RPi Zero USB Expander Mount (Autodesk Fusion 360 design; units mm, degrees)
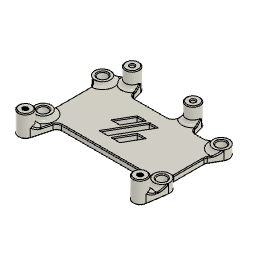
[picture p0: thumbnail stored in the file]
sketch "Sketch1" plane through (0, 0, 0) normal (0, 0, 1) x axis (1, 0, 0)
  line L1 (-32.5, 26.25) -> (32.5, 26.25)
  line L2 (-32.5, -26.25) -> (-32.5, 26.25)
  line L3 (32.5, -26.25) -> (-32.5, -26.25)
  line L4 (32.5, 26.25) -> (32.5, -26.25)
  line L5 (-32.5, -26.25) -> (32.5, 26.25)
  line L6 (32.5, -26.25) -> (-32.5, 26.25)
  line L7 (29, 0.25) -> (-29, 0.25)
  line L8 (29, -22.75) -> (29, 0.25)
  line L9 (-29, -22.75) -> (29, -22.75)
  line L10 (-29, 0.25) -> (-29, -22.75)
  line L11 (-5.77, 23) -> (-20.77, 23)
  line L12 (10.03, 23) -> (-5.77, 23)
  circle C1 centre (-20.77, 23) radius 1.25
  circle C2 centre (-5.77, 23) radius 1.25
  circle C3 centre (10.03, 23) radius 1.25
  circle C4 centre (-29, 0.25) radius 1.25
  circle C5 centre (29, 0.25) radius 1.25
  circle C6 centre (29, -22.75) radius 1.25
  circle C7 centre (-29, -22.75) radius 1.25
  point P6 (0, 0)
  point P1 (0, 0)
  point P10 (-29, 0.25)
  point P11 (-29, 0.25)
  point P12 (29, 0.25)
  point P15 (29, 0.25)
  point P13 (29, -22.75)
  point P16 (29, -22.75)
  point P14 (-29, -22.75)
  point P17 (-29, -22.75)
  point P7 (-20.77, 23)
  point P18 (-20.77, 23)
  point P8 (-5.77, 23)
  point P19 (-5.77, 23)
  point P9 (10.03, 23)
  point P20 (10.03, 23)
  point P4 (-32.5, -26.25)
  point P5 (32.5, -26.25)
  point P2 (32.5, 26.25)
  horizontal L1
  perpendicular L1 L2
  parallel L1 L3
  parallel L2 L4
  coincident L5 P6
  coincident L6 P6
  coincident P1 P6
  horizontal L7
  vertical L8
  horizontal L9
  vertical L10
  coincident P10 P11
  coincident P12 P15
  coincident P13 P16
  coincident P14 P17
  equal C6 C7
  equal C5 C6
  equal C4 C5
  equal C1 C4
  equal C1 C3
  equal C2 C3
  horizontal L11
  parallel L11 L12
  coincident P7 P18
  coincident P8 P19
  coincident P9 P20
  dimension "d1" distance P4 P5 = 65
  dimension "d2" distance P2 P5 = 52.5
  dimension "d3" distance P11 P14 = 23
  dimension "d4" distance P13 P14 = 58
  dimension "d5" diameter C1 = 2.5
  dimension "d10" distance L3 L9 = 3.5
  dimension "d11" distance L2 L10 = 3.5
  dimension "d12" distance P7 P10 = 8.23
  dimension "d13" distance P7 P10 = 22.75
  dimension "d14" distance P18 P19 = 15
  dimension "d15" distance P19 P20 = 15.8
  dimension "d27" diameter P15 = 8
  dimension "d47" angle P15 = 30
  dimension "d48" angle P15 = 30
extrude "Extrude1" new body sketch "Sketch1" profile of L1 L2 L3 L4 C1 C2 C3 C4 C5 C6 C7 along normal blind 1.6
fillet "Fillet1" radius 2
sketch "Sketch1" plane through (0, 0, 0) normal (0, 0, -1) x axis (1, 0, 0)
  line L1 (32.5, 24.25) -> (32.5, -24.25)
  line L2 (-30.5, 26.25) -> (30.5, 26.25)
  line L3 (-32.5, -24.25) -> (-32.5, 24.25)
  line L4 (30.5, -26.25) -> (-30.5, -26.25)
  circle C1 centre (29, -0.25) radius 1.25
  circle C2 centre (29, 22.75) radius 1.25
  circle C3 centre (-5.77, -23) radius 1.25
  circle C4 centre (10.03, -23) radius 1.25
  circle C5 centre (-20.77, -23) radius 1.25
  circle C6 centre (-29, 22.75) radius 1.25
  circle C7 centre (-29, -0.25) radius 1.25
  arc A1 centre (30.5, -24.25) radius 2 clockwise from (32.5, -24.25) to (30.5, -26.25)
  arc A2 centre (30.5, 24.25) radius 2 clockwise from (30.5, 26.25) to (32.5, 24.25)
  arc A3 centre (-30.5, 24.25) radius 2 clockwise from (-32.5, 24.25) to (-30.5, 26.25)
  arc A4 centre (-30.5, -24.25) radius 2 clockwise from (-30.5, -26.25) to (-32.5, -24.25)
  circle C8 centre (-29, 22.75) radius 3.5
  circle C9 centre (29, 22.75) radius 3.5
  circle C10 centre (-20.77, -23) radius 3.5
  circle C11 centre (10.03, -23) radius 3.5
  concentric C6 C8
  concentric C2 C9
  concentric C5 C10
  concentric C4 C11
  equal C9 C11
  equal C10 C11
  equal C8 C10
  dimension "d16" diameter C8 = 7
extrude "Extrude1" new body sketch "Sketch1" profile of C8 C9 C10 C11 along normal blind 11
sketch "Sketch2" plane through (0, 0, -11) normal (0, 0, -1) x axis (1, 0, 0)
  line L1 (30, 12.75) -> (-30, 12.75)
  line L2 (30, -17.25) -> (30, 12.75)
  line L3 (-30, -17.25) -> (30, -17.25)
  line L4 (-30, 12.75) -> (-30, -17.25)
  line L5 (29, 22.75) -> (-29, 22.75)
  line L6 (0, 12.75) -> (0, 22.75)
  line L7 (-22.4821, -26.0527) -> (-31.9567, -20.7387)
  line L8 (-32.461, 23.2711) -> (-33.9554, 13.3455)
  line L9 (33.9554, 13.3455) -> (32.461, 23.2711)
  line L10 (-30, -13.25) -> (-30, 8.75)
  line L11 (30, -13.25) -> (30, 8.75)
  line L12 (26, 12.75) -> (-26, 12.75)
  line L13 (22.697, 12.75) -> (25.6193, 23.6559)
  line L14 (-22.697, 12.75) -> (-25.6193, 23.6559)
  line L15 (26, -17.25) -> (-26, -17.25)
  line L16 (-15.6058, -17.25) -> (-17.3893, -23.9059)
  line L17 (6.6493, -23.9059) -> (4.8658, -17.25)
  line L18 (15.1942, -17.25) -> (13.4107, -23.9059)
  line L19 (30, -9.25) -> (33.4641, -15.25)
  line L20 (22, -17.25) -> (28, -20.7141)
  circle C1 centre (29, 22.75) radius 3.5
  circle C2 centre (-30, 12.75) radius 2.35
  circle C3 centre (-30, -17.25) radius 2.35
  circle C4 centre (30, -17.25) radius 2.35
  circle C5 centre (30, 12.75) radius 2.35
  circle C6 centre (10.03, -23) radius 3.5
  circle C7 centre (-20.77, -23) radius 3.5
  circle C8 centre (-29, 22.75) radius 3.5
  circle C9 centre (-30, -17.25) radius 4
  circle C10 centre (30, -17.25) radius 4
  circle C11 centre (-30, 12.75) radius 4
  circle C12 centre (30, 12.75) radius 4
  point P3 (-30, 12.75)
  point P7 (-30, 12.75)
  point P6 (-30, -17.25)
  point P8 (-30, -17.25)
  point P5 (30, -17.25)
  point P9 (30, -17.25)
  point P4 (30, 12.75)
  point P10 (30, 12.75)
  point P13 (-29, 22.75)
  point P14 (-29, 22.75)
  point P2 (29, 22.75)
  point P15 (29, 22.75)
  point P16 (0, 22.75)
  point P17 (0, 12.75)
  point P23 (-22.4821, -26.0527)
  point P24 (-33.9554, 13.3455)
  point P25 (-32.461, 23.2711)
  point P26 (32.461, 23.2711)
  point P27 (33.9554, 13.3455)
  point P28 (-30, 8.75)
  point P29 (-30, -13.25)
  point P30 (30, 8.75)
  point P31 (30, -13.25)
  point P32 (-26, 12.75)
  point P33 (26, 12.75)
  point P34 (25.6193, 23.6559)
  point P35 (22.697, 12.75)
  point P36 (-25.6193, 23.6559)
  point P37 (-22.697, 12.75)
  point P38 (-26, -17.25)
  point P39 (26, -17.25)
  point P22 (-31.9567, -20.7387)
  point P40 (-17.3893, -23.9059)
  point P41 (-15.6058, -17.25)
  point P42 (4.8658, -17.25)
  point P43 (6.6493, -23.9059)
  point P44 (13.4107, -23.9059)
  point P45 (15.1942, -17.25)
  point P46 (33.4641, -15.25)
  point P47 (30, -9.25)
  point P48 (28, -20.7141)
  point P49 (22, -17.25)
  horizontal L1
  vertical L2
  horizontal L3
  vertical L4
  coincident P3 P7
  coincident P6 P8
  coincident P5 P9
  coincident P4 P10
  equal C2 C3
  equal C3 C5
  equal C4 C5
  coincident P13 P14
  coincident P2 P15
  midpoint L5 P16
  perpendicular L5 L6
  midpoint L1 P17
  concentric C3 C9
  concentric C4 C10
  equal C9 C10
  concentric C2 C11
  concentric C5 C12
  equal C11 C12
  equal C10 C12
  coincident C7 P23
  tangent C7 L7
  coincident C11 P24
  coincident C8 P25
  coincident C1 P26
  coincident C12 P27
  tangent C11 L8
  tangent C8 L8
  tangent C1 L9
  tangent C12 L9
  coincident L4 P28
  coincident C11 P28
  coincident C9 P29
  coincident L4 P29
  coincident L2 P30
  coincident C12 P30
  coincident C10 P31
  coincident L2 P31
  coincident L1 P32
  coincident C11 P32
  coincident L1 P33
  coincident C12 P33
  coincident C1 P34
  coincident L1 P35
  tangent C1 L13
  symmetric L6 P34 P36
  symmetric L6 P35 P37
  coincident L1 P37
  coincident C9 P38
  coincident L3 P38
  coincident C10 P39
  coincident L3 P39
  tangent C9 L7
  coincident C9 P22
  coincident C7 P40
  coincident L3 P41
  tangent C7 L16
  coincident L3 P42
  coincident C6 P43
  tangent C6 L17
  coincident C6 P44
  coincident L3 P45
  tangent C6 L18
  coincident C10 P46
  coincident L2 P47
  coincident C10 P48
  coincident L15 P49
  tangent C10 L20
  tangent C10 L19
  dimension "d19" distance P3 P4 = 60
  dimension "d20" distance P3 P6 = 30
  dimension "d21" diameter C2 = 4.7
  dimension "d27" diameter C10 = 8
  dimension "d28" distance P16 P17 = 10
  dimension "d35" angle L12 L14 = 75
  dimension "d38" angle L15 L16 = 75
  dimension "d39" angle L15 L17 = 75
  dimension "d40" angle L15 L18 = 75
  dimension "d47" angle L11 L19 = 30
  dimension "d48" angle L3 L20 = 30
extrude "Extrude2" add sketch "Sketch2" profile of C1 C2 C3 C4 C5 C6 C7 C8 C9 C10 C11 C12 L7 L8 L9 L10 L11 L12 L13 L14 L15 L16 L17 L18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 against normal blind 3
fillet "Fillet1" radius 2.5
sketch "Sketch4" plane through (0, 0, 0) normal (0, 0, 1) x axis (-1, 0, 0)
  circle C1 centre (-29, 22.75) radius 3.5
  circle C2 centre (29, 22.75) radius 3.5
  circle C3 centre (20.77, -23) radius 3.5
  circle C4 centre (-10.03, -23) radius 3.5
  circle C5 centre (20.77, -23) radius 0.95
  circle C6 centre (-10.03, -23) radius 0.95
  concentric C3 C5
  concentric C4 C6
  equal C5 C6
  dimension "d53" diameter C5 = 1.9
extrude "Extrude3" cut sketch "Sketch4" profile of C5 C6 no distance stored
sketch "Sketch5" plane through (0, 0, -8) normal (0, 0, 1) x axis (-1, 0, 0)
  line L1 (-33.4641, -15.25) -> (-30.3349, -9.8301)
  line L2 (-22.5801, -17.5849) -> (-28, -20.7141)
  line L3 (-17.1125, -17.25) -> (-21.3301, -17.25)
  line L4 (-13.4107, -23.9059) -> (-14.6977, -19.103)
  line L5 (-5.3623, -19.103) -> (-6.6493, -23.9059)
  line L6 (13.6875, -17.25) -> (-2.9475, -17.25)
  line L7 (17.3893, -23.9059) -> (16.1023, -19.103)
  line L8 (31.9567, -20.7387) -> (22.4821, -26.0527)
  line L9 (30, 6.75) -> (30, -11.25)
  line L10 (32.461, 23.2711) -> (33.9554, 13.3455)
  line L11 (23.1935, 14.603) -> (25.6193, 23.6559)
  line L12 (-20.7787, 12.75) -> (20.7787, 12.75)
  line L13 (-25.6193, 23.6559) -> (-23.1935, 14.603)
  line L14 (-33.9554, 13.3455) -> (-32.461, 23.2711)
  line L15 (-30, -8.5801) -> (-30, 6.75)
  circle C1 centre (-30, 12.75) radius 2.35
  circle C2 centre (-30, -17.25) radius 2.35
  circle C3 centre (30, -17.25) radius 2.35
  circle C4 centre (30, 12.75) radius 2.35
  arc A1 centre (-30, -17.25) radius 4 clockwise from (-28, -20.7141) to (-33.4641, -15.25)
  arc A2 centre (-21.3301, -19.75) radius 2.5 clockwise from (-22.5801, -17.5849) to (-21.3301, -17.25)
  arc A3 centre (-17.1125, -19.75) radius 2.5 clockwise from (-17.1125, -17.25) to (-14.6977, -19.103)
  arc A4 centre (-10.03, -23) radius 3.5 clockwise from (-13.4107, -23.9059) to (-6.6493, -23.9059)
  arc A5 centre (-2.9475, -19.75) radius 2.5 clockwise from (-5.3623, -19.103) to (-2.9475, -17.25)
  arc A6 centre (13.6875, -19.75) radius 2.5 clockwise from (13.6875, -17.25) to (16.1023, -19.103)
  arc A7 centre (20.77, -23) radius 3.5 clockwise from (17.3893, -23.9059) to (22.4821, -26.0527)
  arc A8 centre (30, -17.25) radius 4 clockwise from (31.5385, -13.5577) to (31.9567, -20.7387)
  arc A9 centre (32.5, -11.25) radius 2.5 clockwise from (31.5385, -13.5577) to (30, -11.25)
  arc A10 centre (32.5, 6.75) radius 2.5 clockwise from (30, 6.75) to (31.5385, 9.0577)
  arc A11 centre (30, 12.75) radius 4 clockwise from (33.9554, 13.3455) to (31.5385, 9.0577)
  arc A12 centre (29, 22.75) radius 3.5 clockwise from (32.461, 23.2711) to (25.6193, 23.6559)
  arc A13 centre (20.7787, 15.25) radius 2.5 clockwise from (23.1935, 14.603) to (20.7787, 12.75)
  arc A14 centre (-20.7787, 15.25) radius 2.5 clockwise from (-20.7787, 12.75) to (-23.1935, 14.603)
  arc A15 centre (-29, 22.75) radius 3.5 clockwise from (-25.6193, 23.6559) to (-32.461, 23.2711)
  arc A16 centre (-30, 12.75) radius 4 clockwise from (-31.5385, 9.0577) to (-33.9554, 13.3455)
  arc A17 centre (-32.5, 6.75) radius 2.5 clockwise from (-31.5385, 9.0577) to (-30, 6.75)
  arc A18 centre (-32.5, -8.5801) radius 2.5 clockwise from (-30, -8.5801) to (-30.3349, -9.8301)
  circle C5 centre (30, -17.25) radius 4
  circle C6 centre (-30, -17.25) radius 4
  circle C7 centre (30, 12.75) radius 4
  circle C8 centre (-30, 12.75) radius 4
  concentric C3 C5
  concentric C2 C6
  concentric C4 C7
  concentric C1 C8
extrude "Extrude4" add sketch "Sketch5" profile of C1 C2 C3 C4 A1 A8 A11 A16 C5 C6 C7 C8 along normal blind 2
hole "Hole1" HoleDepth 11 HoleDiameter 2.076 TipAngle 180
hole "Hole2" HoleDepth 11 HoleDiameter 2.076 TipAngle 180
sketch "Sketch6" plane through (0, 0, -8) normal (0, 0, 1) x axis (-1, 0, 0)
  line L1 (32.461, 23.2711) -> (33.9554, 13.3455)
  line L2 (23.1935, 14.603) -> (25.6193, 23.6559)
  line L3 (-20.7787, 12.75) -> (20.7787, 12.75)
  line L4 (-25.6193, 23.6559) -> (-23.1935, 14.603)
  line L5 (-33.9554, 13.3455) -> (-32.461, 23.2711)
  line L6 (-30, -8.5801) -> (-30, 6.75)
  line L7 (-33.4641, -15.25) -> (-30.3349, -9.8301)
  line L8 (-22.5801, -17.5849) -> (-28, -20.7141)
  line L9 (-17.1125, -17.25) -> (-21.3301, -17.25)
  line L10 (-13.4107, -23.9059) -> (-14.6977, -19.103)
  line L11 (-5.3623, -19.103) -> (-6.6493, -23.9059)
  line L12 (13.6875, -17.25) -> (-2.9475, -17.25)
  line L13 (17.3893, -23.9059) -> (16.1023, -19.103)
  line L14 (31.9567, -20.7387) -> (22.4821, -26.0527)
  line L15 (30, 6.75) -> (30, -11.25)
  line L16 (4.4422, 5.4442) -> (8.0092, 5.4442)
  line L17 (-4.4423, -9.9442) -> (4.4422, 5.4442)
  line L18 (-0.8753, -9.9442) -> (-4.4423, -9.9442)
  line L19 (8.0092, 5.4442) -> (-0.8753, -9.9442)
  line L20 (-1.6368, 5.4442) -> (1.9302, 5.4442)
  line L21 (-6.079, -2.25) -> (-1.6368, 5.4442)
  line L22 (-2.512, -2.25) -> (0, -2.25)
  line L23 (-6.079, -2.25) -> (-2.512, -2.25)
  line L24 (-2.512, -2.25) -> (1.9302, 5.4442)
  line L25 (6.079, -2.25) -> (3.567, -2.25)
  line L26 (9.646, -2.25) -> (6.079, -2.25)
  line L27 (5.2037, -9.9442) -> (9.646, -2.25)
  line L28 (1.6367, -9.9442) -> (6.079, -2.25)
  line L29 (1.6367, -9.9442) -> (5.2037, -9.9442)
  line L30 (-30, -2.25) -> (30, -2.25)
  arc A1 centre (30, 12.75) radius 4 clockwise from (31.5385, 9.0577) to (33.9554, 13.3455)
  arc A2 centre (29, 22.75) radius 3.5 clockwise from (32.461, 23.2711) to (25.6193, 23.6559)
  arc A3 centre (20.7787, 15.25) radius 2.5 clockwise from (23.1935, 14.603) to (20.7787, 12.75)
  arc A4 centre (-20.7787, 15.25) radius 2.5 clockwise from (-20.7787, 12.75) to (-23.1935, 14.603)
  arc A5 centre (-29, 22.75) radius 3.5 clockwise from (-25.6193, 23.6559) to (-32.461, 23.2711)
  arc A6 centre (-30, 12.75) radius 4 clockwise from (-33.9554, 13.3455) to (-31.5385, 9.0577)
  arc A7 centre (-32.5, 6.75) radius 2.5 clockwise from (-31.5385, 9.0577) to (-30, 6.75)
  arc A8 centre (-32.5, -8.5801) radius 2.5 clockwise from (-30, -8.5801) to (-30.3349, -9.8301)
  arc A9 centre (-30, -17.25) radius 4 clockwise from (-33.4641, -15.25) to (-28, -20.7141)
  arc A10 centre (-21.3301, -19.75) radius 2.5 clockwise from (-22.5801, -17.5849) to (-21.3301, -17.25)
  arc A11 centre (-17.1125, -19.75) radius 2.5 clockwise from (-17.1125, -17.25) to (-14.6977, -19.103)
  arc A12 centre (-10.03, -23) radius 3.5 clockwise from (-13.4107, -23.9059) to (-6.6493, -23.9059)
  arc A13 centre (-2.9475, -19.75) radius 2.5 clockwise from (-5.3623, -19.103) to (-2.9475, -17.25)
  arc A14 centre (13.6875, -19.75) radius 2.5 clockwise from (13.6875, -17.25) to (16.1023, -19.103)
  arc A15 centre (20.77, -23) radius 3.5 clockwise from (17.3893, -23.9059) to (22.4821, -26.0527)
  arc A16 centre (30, -17.25) radius 4 clockwise from (31.9567, -20.7387) to (31.5385, -13.5577)
  arc A17 centre (32.5, -11.25) radius 2.5 clockwise from (31.5385, -13.5577) to (30, -11.25)
  arc A18 centre (32.5, 6.75) radius 2.5 clockwise from (30, 6.75) to (31.5385, 9.0577)
  point P59 (0, -2.25)
  point P62 (3.567, -2.25)
  point P67 (30, -2.25)
  point P68 (-30, -2.25)
  point P53 (8.0092, 5.4442)
  point P54 (4.4422, 5.4442)
  point P55 (-4.4423, -9.9442)
  point P60 (-2.512, -2.25)
  horizontal L16
  horizontal L18
  equal L16 L18
  parallel L16 L20
  parallel L17 L21
  midpoint L17 P59
  horizontal L22
  parallel L22 L23
  equal L16 L23
  equal L20 L23
  midpoint L19 P62
  horizontal L25
  equal L22 L25
  parallel L25 L26
  parallel L19 L27
  equal L24 L27
  equal L18 L26
  equal L27 L28
  parallel L27 L28
  collinear L18 L29
  midpoint L15 P67
  coincident L6 P68
  perpendicular L6 L30
  coincident P59 L30
  midpoint P59 L30
  dimension "d60" distance P53 P54 = 3.567
  dimension "d61" angle L16 L17 = 120
  dimension "d62" distance P54 P55 = 17.769
  dimension "d63" distance P59 P60 = 2.512
extrude "Extrude5" cut sketch "Sketch6" profile of L16 L17 L18 L19 L20 L21 L23 L24 L26 L27 L28 L29 no distance stored
chamfer "Chamfer1" distance 0.4
fillet "Fillet2" radius 2
chamfer "Chamfer2" distance 0.4
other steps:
thread "Thread1"
thread "Thread2"
create_component "CreateComponent1"
create_component "CreateComponent2"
